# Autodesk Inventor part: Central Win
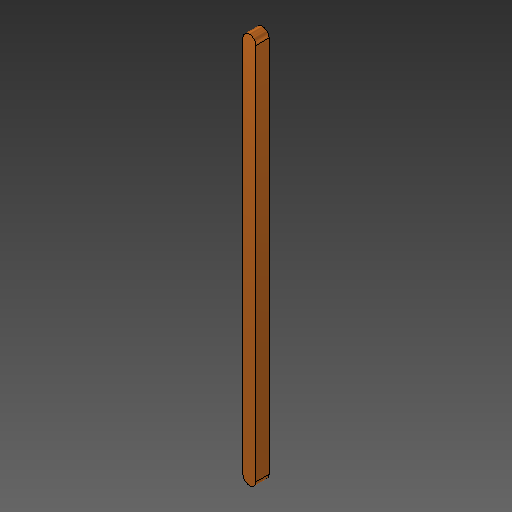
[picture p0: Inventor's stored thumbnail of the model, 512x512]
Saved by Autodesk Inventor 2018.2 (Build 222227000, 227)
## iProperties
Created: 2018-03
Part Number: Central Win
Material: Gold
Document SubType Name: Modeling
Designer: PeterMaxwell-Stewart
Mass: 70.8963 g
Surface Area: 29.7798 cm^2
Volume: 3.67338 cm^3
Density: 19.3 g/cm^3
Appearance: Metal 1600F Hot
Author: PeterMaxwell-Stewart
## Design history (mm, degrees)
derived "O's and X's.ipt"
feature "Central Win::O's and X's.ipt" dims "d0" = 10
tag "TaggingFeature1"
body "Solid1"
